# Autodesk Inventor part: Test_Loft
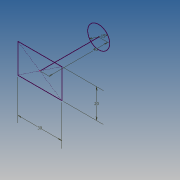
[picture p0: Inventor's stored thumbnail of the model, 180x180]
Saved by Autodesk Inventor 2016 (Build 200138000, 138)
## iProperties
Created: 2015-09
Part Number: Test_Loft
Material: Generic
Document SubType Name: Modeling
Designer: julian.chica
Density: 1 g/cm^3
Appearance: Default
Mass: 16.0746 g
Surface Area: 38.3397 cm^2
Volume: 16.0746 cm^3
Author: julian.chica
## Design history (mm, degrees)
sketch "PERFIL BASE"
  geometry: L1 (15, 10)-(-15, 10); L2 (-15, 10)-(-15, -10); L3 (-15, -10)-(15, -10); L4 (15, -10)-(15, 10); L5 (15, 10)-(-15, -10); L6 (-15, 10)-(15, -10); 1 further point
  constraints: 12 end point, 2 midpoint, 2 parallel, 1 horizontal, 1 perpendicular
  dimensions: "d0" = 30 distance of L3.end L2.end; "d1" = 20 distance of L2.end L1.end
sketch "LINEA CENTRO"
  geometry: L1 (0, 0)-(0, 40)
  constraints: 2 end point, 1 vertical
  dimensions: "d2" = 40 distance of L1.start L1.end
workplane "Work Plane1"
sketch "PERFIL TOPE"
  geometry: C1 r 7.5 at (0, 0); 1 further point
  constraints: 1 centre point, 1 coincident
  dimensions: "d3" = 15 diameter of C1
body "Solid2"
